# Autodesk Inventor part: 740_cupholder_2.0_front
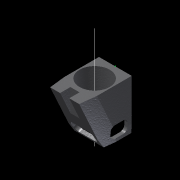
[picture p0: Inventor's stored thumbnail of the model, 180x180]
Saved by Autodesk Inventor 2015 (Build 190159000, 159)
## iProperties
Created: 2016-11
Part Number: 740_cupholder_2.0_front
Material: ABS Plastic
Document SubType Name: Modeling
Designer: Mikael
Density: 1.06 g/cm^3
Appearance: Textured - Gray
Mass: 944.042 g
Surface Area: 2215.58 cm^2
Volume: 890.605 cm^3
Author: Mikael
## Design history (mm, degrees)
sketch "Sketch1"
  geometry: L1 (0, -122.5)-(120, -122.5); L2 (120, -122.5)-(120, 122.5); L3 (120, 122.5)-(0, 67.5); L4 (0, -122.5)-(0, 67.5); 1 further point
  constraints: 8 end point, 2 vertical, 1 perpendicular, 1 point on line
  dimensions: "d0" = 190 distance of L3.end L1.start; "d1" = 120 distance of L1.start L1.end; "d2" = 245 distance of L1.end L2.end; "d13" = 122.5 distance from line of point (0, 0) L1 (= 0.5 x d2)
extrude "Extrusion1" new body sketch "Sketch1" stored distance "d3" = 79; taper "d4" = 0 deg
sketch "Sketch2"
  geometry: L1 (79, 0)-(0, 0) reference; L2 (28.5, 0)-(50.5, 0); L3 (50.5, 0)-(50.5, 25); L4 (50.5, 25)-(28.5, 25); L5 (28.5, 25)-(28.5, 0); L6 (39.5, 294)-(39.5, -49) reference; 1 further point
  constraints: 8 end point, 2 parallel, 1 horizontal, 1 perpendicular, 1 point on line
  dimensions: "d5" = 22 distance between parallel lines of L3 L5; "d6" = 25 distance of L4.end L2.start; "d7" = 11 distance between parallel lines of L6 L5 (= 0.5 x d5)
extrude "Extrusion2" cut sketch "Sketch2" stored distance "d8" = 75; taper "d9" = 0 deg
sketch "Sketch3"
  geometry: L1 (283.012, 50)-(45, 50); L2 (45, 50)-(45, 19); L3 (45, 19)-(200, 8); L4 (200, 8)-(200, 50); L5 (-58.901, 0)-(353.406, 0) reference; L6 (0, -122.5)-(0, 67.5) reference; L7 (45, -50)-(45, -81); L8 (45, -81)-(200, -92); L9 (200, -92)-(200, -50); L10 (294.505, -50)-(45, -50); L11 (120, 83.999)-(120, -122.5) reference; 2 further points
  constraints: 16 end point, 4 vertical, 2 horizontal, 2 point on line
  dimensions: "d10" = 62 diameter of L2.end L1; "d11" = 84 diameter of L3.end L1; "d14" = 50 distance from line of L5 L1.end; "d16" = 155 distance between parallel lines of L4 L2; "d18" = 45 distance between parallel lines of L6 L2 (derived); "d19" = 62 diameter of L7.end L10; "d20" = 84 diameter of L8.end L10; "d21" = 155 distance between parallel lines of L9 L7; "d22" = 45 distance between parallel lines of L6 L7 (= d18); "d23" = 50 distance from line of L5 L7.start (derived); "d61" = 75 distance between parallel lines of L2 L11; "d62" = 100 distance of L7.start L1.end
sketch "Sketch5"
  geometry: 1 further point
node "plan urtag fram"
sketch "Sketch6"
  geometry: L1 (-39.5, 0)-(-11, 0) reference; L2 (-39.5, -222.721)-(-39.5, 0) reference; L3 (39.5, 0)-(-39.5, 0) reference; L4 (-35, 0)-(-39.5, -35); L5 (-39.5, 0)-(-35, 0); L6 (-39.5, 0)-(-39.5, -35); L7 (39.5, 0)-(39.5, -222.721) reference; L8 (11, 0)-(39.5, 0) reference; L9 (35, 0)-(39.5, -35); L10 (39.5, -35)-(39.5, 0); L11 (35, 0)-(39.5, 0); 1 further point
  constraints: 12 end point, 4 collinear, 4 point on line
  dimensions: "d30" = 70 distance of L9.start L4.start; "d31" = 35 horizontal distance of L9.start point (0, -61.362) (derived); "d32" = 35 distance of L9.end L3.start; "d33" = 35 distance of L1.start L4.end (derived)
extrude "Extrusion4" cut sketch "Sketch6" stored distance "d34" = 10; taper "d35" = 0 deg
node "plan urtab gångjärn"
sketch "Sketch7"
  geometry: L1 (79, 0)-(79, -206.499) reference; L2 (79, 0)-(0, 0) reference; L3 (0, -206.499)-(0, 0) reference; L4 (69, -10)-(52, -10); L5 (52, -10)-(52, 0); L6 (52, 0)-(69, 0); L7 (69, 0)-(69, -10); L8 (27, -10)-(10, -10); L9 (10, -10)-(10, 0); L10 (10, 0)-(27, 0); L11 (27, 0)-(27, -10); 1 further point
  constraints: 16 end point, 4 parallel, 2 horizontal, 2 perpendicular, 2 point on line
  dimensions: "d38" = 17 distance of L5.end L6.end; "d40" = 17 distance of L8.start L8.end (derived); "d41" = 10 distance of L6.end L4.start; "d42" = 10 distance of L8.end L9.end (derived); "d45" = 25 distance between parallel lines of L11 L5; "d46" = 12.5 distance from line of point (39.5, -122.5) L5 (derived); "d47" = 10 distance between parallel lines of L1 L7 (derived)
extrude "Extrusion5" cut sketch "Sketch7" distance "d43" = 18; taper "d44" = 0 deg
chamfer "Chamfer1" distance "d49" = 20; stored, may be unused: second distance "d50" = 5, angle "d51" = 20 deg
chamfer "Chamfer2" distance "d52" = 20; stored, may be unused: second distance "d53" = 1, angle "d54" = 20 deg
chamfer "Chamfer3" distance "d55" = 20; stored, may be unused: second distance "d56" = 1, angle "d57" = 20 deg
chamfer "Chamfer4" distance "d58" = 25; stored, may be unused: second distance "d59" = 4, angle "d60" = 20 deg
revolve "Revolution1" stored, may be unused: angle "d15" = 90 deg
revolve "Revolution2" stored, may be unused: angle "d24" = 90 deg
shell "Shell3" dims "d26" = 8
fillet "Fillet3" dims "d70" = 10
sketch "Sketch17"
  geometry: L1 (-24, 0)-(144, 0) reference; 1 further point
split "Split4" sketch "Sketch17"
sketch "Sketch23"
  geometry: L1 (10, 11.492)-(45.925, 11.492); L2 (55.925, 1.492)-(55.925, -9.21); L3 (45.925, -19.21)-(10, -19.21); L4 (0, -9.21)-(0, 1.492); L5 (55.925, 93.994)-(55.925, 0) reference; L6 (0, 0)-(0, 93.994) reference; L7 (63.43, -27.21)-(-7.505, -27.21) reference; A1 r 10 centre (45.925, 1.492) between (55.925, 1.492) and (45.925, 11.492); A2 r 10 centre (10, 1.492) between (10, 11.492) and (0, 1.492); A3 r 10 centre (10, -9.21) between (0, -9.21) and (10, -19.21); A4 r 10 centre (45.925, -9.21) between (45.925, -19.21) and (55.925, -9.21); 7 further points; 1 other entity
  constraints: 8 end point, 8 point on circle, 8 point on line, 8 tangent, 4 centre point, 3 equal radius, 2 collinear, 2 horizontal, 2 parallel, 1 perpendicular, 1 other
  dimensions: "d90" = 30.70112 distance of point (55.925, 11.492) point (55.925, -19.21) (derived); "d91" = 8 distance between parallel lines of L7 L3; "d92" = 10 radius of A1
extrude "Extrusion11" cut sketch "Sketch23" stored distance "d85" = 10; taper "d86" = 0 deg
sketch "Sketch24"
  geometry: L1 (-6.963, -65.669)-(28.963, -65.669); L2 (38.963, -55.669)-(38.963, -43.669); L3 (38.963, -43.669)-(-16.963, -43.669); L4 (-16.963, -43.669)-(-16.963, -55.669); L5 (-16.963, -55.669)-(-16.963, -47.002) reference; L6 (38.963, -47.002)-(38.963, -55.669) reference; L7 (-24.468, -73.669)-(46.468, -73.669) reference; A1 r 10 centre (-6.963, -55.669) between (-16.963, -55.669) and (-6.963, -65.669); A2 r 10 centre (28.963, -55.669) between (28.963, -65.669) and (38.963, -55.669); 3 further points
  constraints: 8 end point, 4 point on circle, 4 point on line, 4 tangent, 2 centre point, 2 collinear, 2 parallel, 1 equal radius, 1 horizontal, 1 perpendicular
  dimensions: "d93" = 30 distance between parallel lines of L7 L3; "d94" = 8 distance between parallel lines of L1 L7; "d95" = 10 radius of A1
extrude "Extrusion12" cut sketch "Sketch24" distance "d87" = 12; taper "d88" = 0 deg
workaxis "Work Axis1"
sketch "Sketch25"
  geometry: L1 (-50, -24)-(-50, 144) reference; L2 (-50, 37)-(-10, 37); L3 (-10, 37)-(-10, 8); L4 (-10, 8)-(-50, 8); L5 (-50, 8)-(-50, 37); L6 (-37.555, 0)-(0, 0) reference; L7 (-45.394, 37)-(-27.947, 37) reference; L8 (0, 20)-(0, 120) reference
  constraints: 8 end point, 2 parallel, 1 collinear, 1 horizontal, 1 perpendicular, 1 point on line
  dimensions: "d121" = 8 distance between parallel lines of L6 L4; "d124" = 10 distance between parallel lines of L3 L8
extrude "Extrusion14" cut sketch "Sketch25" distance "d119" = 12; taper "d120" = 0 deg
fillet "Fillet5" dims "d123" = 10
mirror "Mirror5"
body "Solid1"
other parameters: "d29" = 90 deg, "d36" = 0
